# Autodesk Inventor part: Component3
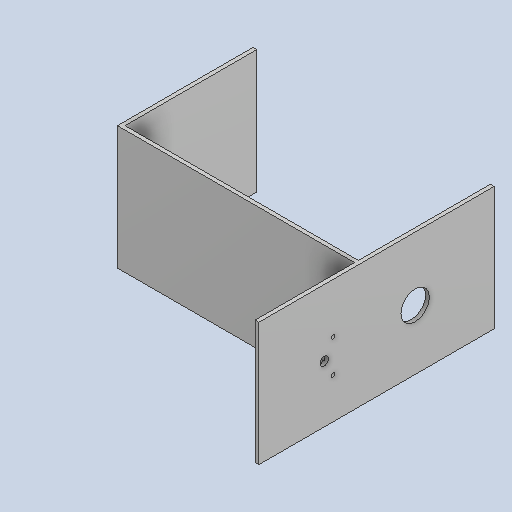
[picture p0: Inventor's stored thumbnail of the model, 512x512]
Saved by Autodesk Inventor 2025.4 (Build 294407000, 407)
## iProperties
Created: 2026-06
Part Number: Component3
Material: Generic
Document SubType Name: Modeling
Designer: AdminForWorker
Density: 1 g/cm^3
Appearance: Default
Title: Component3
Author: AdminForWorker
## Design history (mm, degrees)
feature "Body1"
body "Solid1"
